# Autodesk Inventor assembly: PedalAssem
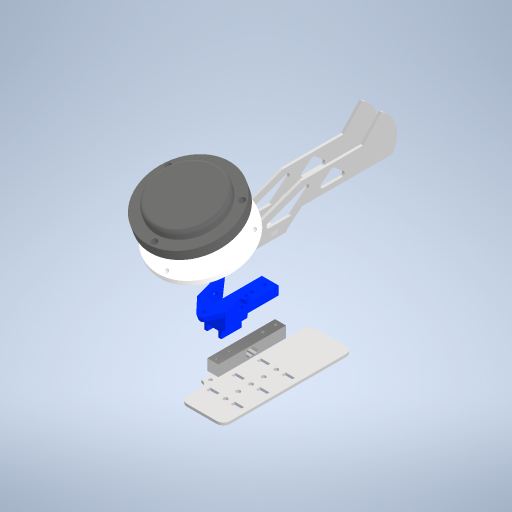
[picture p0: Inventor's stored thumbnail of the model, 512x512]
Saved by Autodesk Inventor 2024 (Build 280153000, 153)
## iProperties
Created: 2023-06
Part Number: PedalAssem
Document SubType Name: Assembly
Designer: Admin
Author: Admin
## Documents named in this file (8)
- C:\Users\Admin\Dropbox\PostDoc\PedalCompliance project\CAD\PedalAssem.iam
- C:\Users\Admin\Dropbox\PostDoc\PedalCompliance project\CAD\DaytonAudio.ipt
- C:\Users\Admin\Dropbox\PostDoc\PedalCompliance project\CAD\PedalPlateModel.ipt
- C:\Users\Admin\Dropbox\PostDoc\PedalCompliance project\CAD\PedalBackPlate.ipt
- C:\Users\Admin\Dropbox\PostDoc\PedalCompliance project\CAD\PedalSmallPlate.ipt
- C:\Users\Admin\Dropbox\PostDoc\PedalCompliance project\CAD\LoadCell2PedalPlate_VAconnect.ipt
- C:\Users\Admin\Dropbox\PostDoc\PedalCompliance project\CAD\DaytonConPlexi.ipt
- C:\Users\Admin\Dropbox\PostDoc\PedalCompliance project\CAD\LoadCell.ipt
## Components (8 placed, 7 different names)
1. DaytonAudio:1 — Mate:18, Mate:19
2. PedalPlateModel:1 — Mate:11, Mate:12
3. PedalBackPlate:1 — Mate:9, Mate:10, Flush:2
4. PedalBackPlate:2 — Mate:7, Flush:1, Mate:8
5. PedalSmallPlate:1 — Mate:7, Flush:1, Mate:8, Mate:9, Mate:10, Flush:2, Mate:15, Mate:16
6. LoadCell2PedalPlate_VAconnect:1 — Mate:13, Mate:14, Mate:15, Mate:16, Mate:17
7. DaytonConPlexi:1 — Mate:17, Mate:18, Mate:19
8. LoadCell:1 — Mate:11, Mate:12, Mate:13, Mate:14
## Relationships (15: Mate 13, Flush 2)
- Mate:7: PedalBackPlate:2 ↔ PedalSmallPlate:1
- Flush:1: PedalBackPlate:2 ↔ PedalSmallPlate:1
- Mate:8: PedalBackPlate:2 ↔ PedalSmallPlate:1
- Mate:9: PedalBackPlate:1 ↔ PedalSmallPlate:1
- Mate:10: PedalBackPlate:1 ↔ PedalSmallPlate:1
- Flush:2: PedalBackPlate:1 ↔ PedalSmallPlate:1
- Mate:11: PedalPlateModel:1 ↔ LoadCell:1
- Mate:12: PedalPlateModel:1 ↔ LoadCell:1
- Mate:13: LoadCell2PedalPlate_VAconnect:1 ↔ LoadCell:1
- Mate:14: LoadCell2PedalPlate_VAconnect:1 ↔ LoadCell:1
- Mate:15: PedalSmallPlate:1 ↔ LoadCell2PedalPlate_VAconnect:1
- Mate:16: PedalSmallPlate:1 ↔ LoadCell2PedalPlate_VAconnect:1
- Mate:17: LoadCell2PedalPlate_VAconnect:1 ↔ DaytonConPlexi:1
- Mate:18: DaytonAudio:1 ↔ DaytonConPlexi:1
- Mate:19: DaytonAudio:1 ↔ DaytonConPlexi:1
